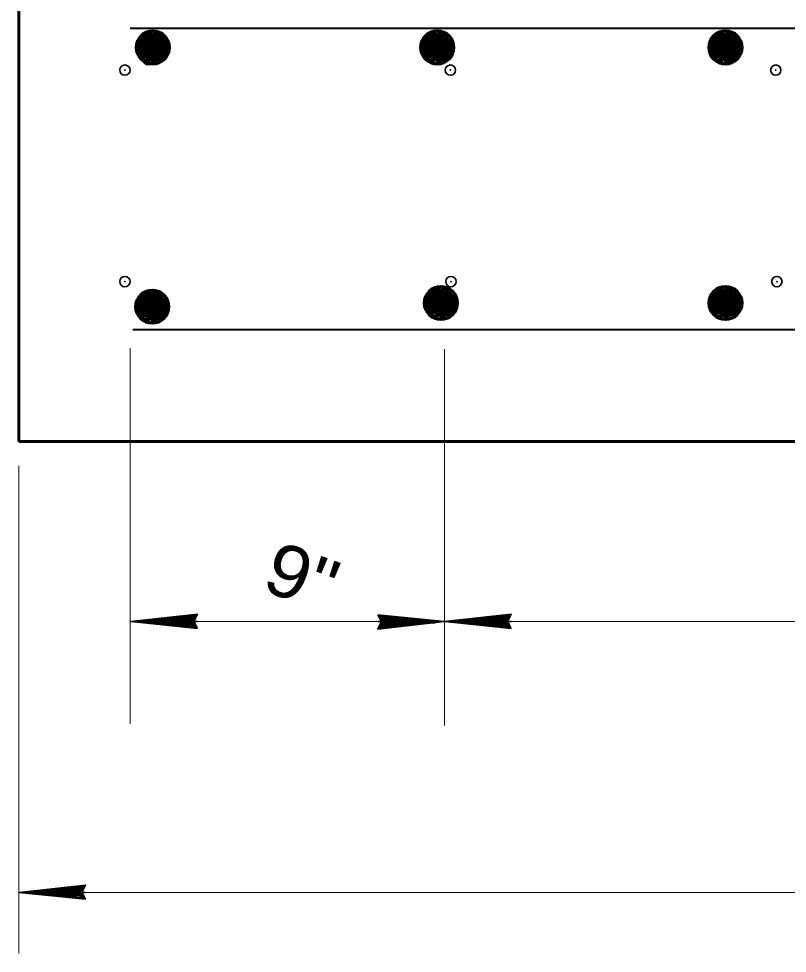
# Model space of a CAD drawing. Extents: x 4.49 to 7.69, y 0.28 to 2.27.
# Drawn here: x 6.3495 to 6.4715, y 1.791 to 1.9394 of the extents above; entities that cross this region are included whole.
import ezdxf
from ezdxf.enums import TextEntityAlignment as Align

# ---------------------------------------------------------------- set-up
doc = ezdxf.new("R2010")
doc.units = 0
doc.header["$LTSCALE"] = 0.0033
doc.header["$PDMODE"] = 32
doc.header["$PDSIZE"] = 0.00165
doc.layers.add('1', color=7, linetype='Continuous', lineweight=35)

msp = doc.modelspace()

# ---------------------------------------------------------------- linework, layer by layer
at = {"layer": '1', "lineweight": 60}
for p, q in [((6.3495, 1.87225), (6.3495, 1.955583)), ((6.368917, 1.936417), (6.36875, 1.9335)), ((6.369167, 1.936417), (6.368917, 1.9335)), ((6.369333, 1.936417), (6.369167, 1.933417)), ((6.3695, 1.936417), (6.36925, 1.933417)), ((6.369667, 1.936417), (6.3695, 1.933417)), ((6.369917, 1.936417), (6.36975, 1.933417)), ((6.370167, 1.936417), (6.369917, 1.933417)), ((6.37025, 1.936333), (6.370083, 1.933417)), ((6.370417, 1.936333), (6.37025, 1.933417)), ((6.370583, 1.936333), (6.370417, 1.933417)), ((6.370833, 1.936333), (6.370583, 1.933417)), ((6.371, 1.936333), (6.370833, 1.933417)), ((6.37125, 1.93625), (6.371, 1.933333)), ((6.3715, 1.93625), (6.37125, 1.933333)), ((6.371667, 1.93625), (6.3715, 1.933333)), ((6.37175, 1.93625), (6.371583, 1.933333)), ((6.371917, 1.93625), (6.37175, 1.933333)), ((6.372, 1.93625), (6.371833, 1.933333)), ((6.37225, 1.936167), (6.372, 1.93325)), ((6.372417, 1.936167), (6.37225, 1.93325)), ((6.372583, 1.936167), (6.372333, 1.93325)), ((6.37275, 1.936167), (6.372583, 1.93325)), ((6.373, 1.936167), (6.372833, 1.93325)), ((6.37325, 1.93425), (6.373083, 1.936083)), ((6.414083, 1.936417), (6.413917, 1.9335)), ((6.414333, 1.936417), (6.414083, 1.9335)), ((6.4145, 1.936417), (6.414333, 1.933417)), ((6.414667, 1.936417), (6.414417, 1.933417)), ((6.414833, 1.936417), (6.414667, 1.933417)), ((6.415083, 1.936417), (6.414917, 1.933417)), ((6.415333, 1.936417), (6.415083, 1.933417)), ((6.415417, 1.936333), (6.41525, 1.933417)), ((6.415583, 1.936333), (6.415417, 1.933417)), ((6.41575, 1.936333), (6.415583, 1.933417)), ((6.416, 1.936333), (6.41575, 1.933417)), ((6.416167, 1.936333), (6.416, 1.933417)), ((6.416417, 1.93625), (6.416167, 1.933333)), ((6.416667, 1.93625), (6.416417, 1.933333)), ((6.416833, 1.93625), (6.416667, 1.933333)), ((6.416917, 1.93625), (6.41675, 1.933333)), ((6.417083, 1.93625), (6.416917, 1.933333)), ((6.417167, 1.93625), (6.417, 1.933333)), ((6.417417, 1.936167), (6.417167, 1.93325)), ((6.417583, 1.936167), (6.417417, 1.93325)), ((6.41775, 1.936167), (6.4175, 1.93325)), ((6.417917, 1.936167), (6.41775, 1.93325)), ((6.418167, 1.936167), (6.418, 1.93325)), ((6.418417, 1.93425), (6.41825, 1.936083)), ((6.459833, 1.936417), (6.459667, 1.9335)), ((6.460083, 1.936417), (6.459833, 1.9335)), ((6.46025, 1.936417), (6.460083, 1.933417)), ((6.460417, 1.936417), (6.460167, 1.933417)), ((6.460583, 1.936417), (6.460417, 1.933417)), ((6.460833, 1.936417), (6.460667, 1.933417)), ((6.461083, 1.936417), (6.460833, 1.933417)), ((6.461167, 1.936333), (6.461, 1.933417)), ((6.461333, 1.936333), (6.461167, 1.933417)), ((6.4615, 1.936333), (6.461333, 1.933417)), ((6.46175, 1.936333), (6.4615, 1.933417)), ((6.461917, 1.936333), (6.46175, 1.933417)), ((6.462167, 1.93625), (6.461917, 1.933333)), ((6.462417, 1.93625), (6.462167, 1.933333)), ((6.462583, 1.93625), (6.462417, 1.933333)), ((6.462667, 1.93625), (6.4625, 1.933333)), ((6.462833, 1.93625), (6.462667, 1.933333)), ((6.462917, 1.93625), (6.46275, 1.933333)), ((6.463167, 1.936167), (6.462917, 1.93325)), ((6.463333, 1.936167), (6.463167, 1.93325)), ((6.4635, 1.936167), (6.46325, 1.93325)), ((6.463667, 1.936167), (6.4635, 1.93325)), ((6.463917, 1.936167), (6.46375, 1.93325)), ((6.464167, 1.93425), (6.464, 1.936083)), ((6.37325, 1.93425), (6.3685, 1.9335)), ((6.418417, 1.93425), (6.413667, 1.9335)), ((6.464167, 1.93425), (6.459417, 1.9335)), ((6.414667, 1.895833), (6.4145, 1.892917)), ((6.414917, 1.895833), (6.414667, 1.892917)), ((6.415083, 1.895833), (6.414917, 1.892833)), ((6.41525, 1.895833), (6.415, 1.892833)), ((6.415417, 1.895833), (6.41525, 1.892833)), ((6.415667, 1.895833), (6.4155, 1.892833)), ((6.415917, 1.895833), (6.415667, 1.892833)), ((6.416, 1.89575), (6.415833, 1.892833)), ((6.416167, 1.89575), (6.416, 1.892833)), ((6.416333, 1.89575), (6.416167, 1.892833)), ((6.416583, 1.89575), (6.416333, 1.892833)), ((6.41675, 1.89575), (6.416583, 1.892833)), ((6.417, 1.895667), (6.41675, 1.89275)), ((6.41725, 1.895667), (6.417, 1.89275)), ((6.417417, 1.895667), (6.41725, 1.89275)), ((6.4175, 1.895667), (6.417333, 1.89275)), ((6.417667, 1.895667), (6.4175, 1.89275)), ((6.41775, 1.895667), (6.417583, 1.89275)), ((6.418, 1.895583), (6.41775, 1.892667)), ((6.418167, 1.895583), (6.418, 1.892667)), ((6.418333, 1.895583), (6.418083, 1.892667)), ((6.4185, 1.895583), (6.418333, 1.892667)), ((6.41875, 1.895583), (6.418583, 1.892667)), ((6.419, 1.893667), (6.418833, 1.8955)), ((6.459833, 1.895833), (6.459667, 1.892917)), ((6.460083, 1.895833), (6.459833, 1.892917)), ((6.46025, 1.895833), (6.460083, 1.892833)), ((6.460417, 1.895833), (6.460167, 1.892833)), ((6.460583, 1.895833), (6.460417, 1.892833)), ((6.460833, 1.895833), (6.460667, 1.892833)), ((6.461083, 1.895833), (6.460833, 1.892833)), ((6.461167, 1.89575), (6.461, 1.892833)), ((6.461333, 1.89575), (6.461167, 1.892833)), ((6.4615, 1.89575), (6.461333, 1.892833)), ((6.46175, 1.89575), (6.4615, 1.892833)), ((6.461917, 1.89575), (6.46175, 1.892833)), ((6.462167, 1.895667), (6.461917, 1.89275)), ((6.462417, 1.895667), (6.462167, 1.89275)), ((6.462583, 1.895667), (6.462417, 1.89275)), ((6.462667, 1.895667), (6.4625, 1.89275)), ((6.462833, 1.895667), (6.462667, 1.89275)), ((6.462917, 1.895667), (6.46275, 1.89275)), ((6.463167, 1.895583), (6.462917, 1.892667)), ((6.463333, 1.895583), (6.463167, 1.892667)), ((6.4635, 1.895583), (6.46325, 1.892667)), ((6.463667, 1.895583), (6.4635, 1.892667)), ((6.463917, 1.895583), (6.46375, 1.892667)), ((6.464167, 1.893667), (6.464, 1.8955)), ((6.368833, 1.89525), (6.368667, 1.892333)), ((6.369083, 1.89525), (6.368833, 1.892333)), ((6.36925, 1.89525), (6.369083, 1.89225)), ((6.369417, 1.89525), (6.369167, 1.89225)), ((6.369583, 1.89525), (6.369417, 1.89225)), ((6.369833, 1.89525), (6.369667, 1.89225)), ((6.370083, 1.89525), (6.369833, 1.89225)), ((6.370167, 1.895167), (6.37, 1.89225)), ((6.370333, 1.895167), (6.370167, 1.89225)), ((6.3705, 1.895167), (6.370333, 1.89225)), ((6.37075, 1.895167), (6.3705, 1.89225)), ((6.370917, 1.895167), (6.37075, 1.89225)), ((6.371167, 1.895083), (6.370917, 1.892167)), ((6.371417, 1.895083), (6.371167, 1.892167)), ((6.371583, 1.895083), (6.371417, 1.892167)), ((6.371667, 1.895083), (6.3715, 1.892167)), ((6.371833, 1.895083), (6.371667, 1.892167)), ((6.371917, 1.895083), (6.37175, 1.892167)), ((6.372167, 1.895), (6.371917, 1.892083)), ((6.372333, 1.895), (6.372167, 1.892083)), ((6.3725, 1.895), (6.37225, 1.892083)), ((6.372667, 1.895), (6.3725, 1.892083)), ((6.372917, 1.895), (6.37275, 1.892083)), ((6.373167, 1.893083), (6.373, 1.894917)), ((6.373167, 1.893083), (6.368417, 1.892333)), ((6.419, 1.893667), (6.41425, 1.892917)), ((6.464167, 1.893667), (6.459417, 1.892917))]:
    msp.add_line(p, q, dxfattribs=at)
at = {"layer": '1', "lineweight": 40}
for p, q in [((6.367167, 1.937917), (6.831833, 1.937917)), ((6.371, 1.935917), (6.372333, 1.936917)), ((6.373083, 1.936083), (6.371833, 1.93725)), ((6.416167, 1.935917), (6.4175, 1.936917)), ((6.41825, 1.936083), (6.417, 1.93725)), ((6.461917, 1.935917), (6.46325, 1.936917)), ((6.464, 1.936083), (6.46275, 1.93725)), ((6.368667, 1.936417), (6.37325, 1.93425)), ((6.368833, 1.935417), (6.372667, 1.93475)), ((6.368917, 1.936), (6.372833, 1.93525)), ((6.368917, 1.935833), (6.372833, 1.935083)), ((6.368917, 1.935583), (6.37275, 1.934833)), ((6.369, 1.936417), (6.372917, 1.93575)), ((6.369, 1.93625), (6.372917, 1.9355)), ((6.369083, 1.93675), (6.372917, 1.936083)), ((6.413833, 1.936417), (6.418417, 1.93425)), ((6.414, 1.935417), (6.417833, 1.93475)), ((6.414083, 1.936), (6.418, 1.93525)), ((6.414083, 1.935833), (6.418, 1.935083)), ((6.414083, 1.935583), (6.417917, 1.934833)), ((6.414167, 1.936417), (6.418083, 1.93575)), ((6.414167, 1.93625), (6.418083, 1.9355)), ((6.41425, 1.93675), (6.418083, 1.936083)), ((6.459583, 1.936417), (6.464167, 1.93425)), ((6.45975, 1.935417), (6.463583, 1.93475)), ((6.459833, 1.936), (6.46375, 1.93525)), ((6.459833, 1.935833), (6.46375, 1.935083)), ((6.459833, 1.935583), (6.463667, 1.934833)), ((6.459917, 1.936417), (6.463833, 1.93575)), ((6.459917, 1.93625), (6.463833, 1.9355)), ((6.46, 1.93675), (6.463833, 1.936083)), ((6.368583, 1.934167), (6.3725, 1.933417)), ((6.368583, 1.934), (6.372417, 1.93325)), ((6.368667, 1.934583), (6.372583, 1.933833)), ((6.36875, 1.935), (6.372583, 1.93425)), ((6.36875, 1.934833), (6.372583, 1.934083)), ((6.368833, 1.93525), (6.372667, 1.9345)), ((6.41375, 1.934167), (6.417667, 1.933417)), ((6.41375, 1.934), (6.417583, 1.93325)), ((6.413833, 1.934583), (6.41775, 1.933833)), ((6.413917, 1.935), (6.41775, 1.93425)), ((6.413917, 1.934833), (6.41775, 1.934083)), ((6.414, 1.93525), (6.417833, 1.9345)), ((6.4595, 1.934167), (6.463417, 1.933417)), ((6.4595, 1.934), (6.463333, 1.93325)), ((6.459583, 1.934583), (6.4635, 1.933833)), ((6.459667, 1.935), (6.4635, 1.93425)), ((6.459667, 1.934833), (6.4635, 1.934083)), ((6.45975, 1.93525), (6.463583, 1.9345)), ((6.3685, 1.933667), (6.372333, 1.932917)), ((6.3685, 1.9335), (6.372333, 1.93275)), ((6.368583, 1.93375), (6.372417, 1.933083)), ((6.372833, 1.93325), (6.369083, 1.932833)), ((6.413667, 1.933667), (6.4175, 1.932917)), ((6.413667, 1.9335), (6.4175, 1.93275)), ((6.41375, 1.93375), (6.417583, 1.933083)), ((6.418, 1.93325), (6.41425, 1.932833)), ((6.459417, 1.933667), (6.46325, 1.932917)), ((6.459417, 1.9335), (6.46325, 1.93275)), ((6.4595, 1.93375), (6.463333, 1.933083)), ((6.46375, 1.93325), (6.46, 1.932833)), ((6.369, 1.895583), (6.372833, 1.894917)), ((6.370917, 1.89475), (6.37225, 1.89575)), ((6.373, 1.894917), (6.37175, 1.896083)), ((6.414417, 1.895833), (6.419, 1.893667)), ((6.414667, 1.895417), (6.418583, 1.894667)), ((6.41475, 1.895833), (6.418667, 1.895167)), ((6.41475, 1.895667), (6.418667, 1.894917)), ((6.414833, 1.896167), (6.418667, 1.8955)), ((6.41675, 1.895333), (6.418083, 1.896333)), ((6.418833, 1.8955), (6.417583, 1.896667)), ((6.459583, 1.895833), (6.464167, 1.893667)), ((6.459833, 1.895417), (6.46375, 1.894667)), ((6.459917, 1.895833), (6.463833, 1.895167)), ((6.459917, 1.895667), (6.463833, 1.894917)), ((6.46, 1.896167), (6.463833, 1.8955)), ((6.461917, 1.895333), (6.46325, 1.896333)), ((6.464, 1.8955), (6.46275, 1.896667)), ((6.368583, 1.89525), (6.373167, 1.893083)), ((6.368667, 1.893833), (6.3725, 1.893083)), ((6.36875, 1.89425), (6.372583, 1.893583)), ((6.36875, 1.894083), (6.372583, 1.893333)), ((6.368833, 1.894833), (6.37275, 1.894083)), ((6.368833, 1.894667), (6.37275, 1.893917)), ((6.368833, 1.894417), (6.372667, 1.893667)), ((6.368917, 1.89525), (6.372833, 1.894583)), ((6.368917, 1.895083), (6.372833, 1.894333)), ((6.414417, 1.894), (6.418333, 1.89325)), ((6.4145, 1.894417), (6.418333, 1.893667)), ((6.4145, 1.89425), (6.418333, 1.8935)), ((6.414583, 1.894833), (6.418417, 1.894167)), ((6.414583, 1.894667), (6.418417, 1.893917)), ((6.414667, 1.89525), (6.418583, 1.8945)), ((6.414667, 1.895), (6.4185, 1.89425)), ((6.459583, 1.894), (6.4635, 1.89325)), ((6.459667, 1.894417), (6.4635, 1.893667)), ((6.459667, 1.89425), (6.4635, 1.8935)), ((6.45975, 1.894833), (6.463583, 1.894167)), ((6.45975, 1.894667), (6.463583, 1.893917)), ((6.459833, 1.89525), (6.46375, 1.8945)), ((6.459833, 1.895), (6.463667, 1.89425)), ((6.368417, 1.8925), (6.37225, 1.89175)), ((6.368417, 1.892333), (6.37225, 1.891583)), ((6.3685, 1.893), (6.372417, 1.89225)), ((6.3685, 1.892833), (6.372333, 1.892083)), ((6.3685, 1.892583), (6.372333, 1.891917)), ((6.368583, 1.893417), (6.3725, 1.892667)), ((6.368667, 1.893667), (6.3725, 1.892917)), ((6.41425, 1.893083), (6.418083, 1.892333)), ((6.41425, 1.892917), (6.418083, 1.892167)), ((6.414333, 1.893583), (6.41825, 1.892833)), ((6.414333, 1.893417), (6.418167, 1.892667)), ((6.414333, 1.893167), (6.418167, 1.8925)), ((6.418583, 1.892667), (6.414833, 1.89225)), ((6.459417, 1.893083), (6.46325, 1.892333)), ((6.459417, 1.892917), (6.46325, 1.892167)), ((6.4595, 1.893583), (6.463417, 1.892833)), ((6.4595, 1.893417), (6.463333, 1.892667)), ((6.4595, 1.893167), (6.463333, 1.8925)), ((6.46375, 1.892667), (6.46, 1.89225)), ((6.37275, 1.892083), (6.369, 1.891667)), ((6.367583, 1.890083), (6.831667, 1.890083))]:
    msp.add_line(p, q, dxfattribs=at)
at = {"layer": '1', "lineweight": 13}
for p, q in [((6.367167, 1.887083), (6.367167, 1.827417)), ((6.417083, 1.886917), (6.417083, 1.827167)), ((6.3495, 1.868417), (6.3495, 1.791)), ((6.367583, 1.843667), (6.831667, 1.843667)), ((6.349417, 1.800667), (6.84875, 1.800667))]:
    msp.add_line(p, q, dxfattribs=at)
at = {"layer": '1'}
for p, q in [((6.377833, 1.843667), (6.36725, 1.843667)), ((6.377583, 1.842833), (6.36975, 1.843833)), ((6.377583, 1.842833), (6.36975, 1.843667)), ((6.377583, 1.842667), (6.36975, 1.843583)), ((6.377583, 1.842667), (6.36975, 1.843583)), ((6.377583, 1.84275), (6.36975, 1.843583)), ((6.377583, 1.84475), (6.37025, 1.843917)), ((6.377583, 1.844583), (6.37025, 1.843833)), ((6.377583, 1.8445), (6.37025, 1.843667)), ((6.377667, 1.844333), (6.370333, 1.843583)), ((6.4065, 1.843667), (6.417083, 1.843667)), ((6.406667, 1.843), (6.414, 1.84375)), ((6.40675, 1.844667), (6.414583, 1.84375)), ((6.40675, 1.844667), (6.414583, 1.84375)), ((6.40675, 1.844583), (6.414583, 1.84375)), ((6.40675, 1.8445), (6.414583, 1.843667)), ((6.40675, 1.8445), (6.414583, 1.8435)), ((6.40675, 1.842833), (6.414083, 1.843667)), ((6.40675, 1.84275), (6.414083, 1.8435)), ((6.40675, 1.842583), (6.414083, 1.843417)), ((6.427667, 1.843667), (6.417083, 1.843667)), ((6.427417, 1.842833), (6.419583, 1.843833)), ((6.427417, 1.842833), (6.419583, 1.843667)), ((6.427417, 1.842667), (6.419583, 1.843583)), ((6.427417, 1.842667), (6.419583, 1.843583)), ((6.427417, 1.84275), (6.419583, 1.843583)), ((6.427417, 1.84475), (6.420083, 1.843917)), ((6.427417, 1.844583), (6.420083, 1.843833)), ((6.427417, 1.8445), (6.420083, 1.843667)), ((6.4275, 1.844333), (6.420167, 1.843583)), ((6.360083, 1.800667), (6.3495, 1.800667)), ((6.359833, 1.799833), (6.352, 1.800833)), ((6.359833, 1.799833), (6.352, 1.800667)), ((6.359833, 1.799667), (6.352, 1.800583)), ((6.359833, 1.799667), (6.352, 1.800583)), ((6.359833, 1.79975), (6.352, 1.800583)), ((6.359833, 1.80175), (6.3525, 1.800917)), ((6.359833, 1.801583), (6.3525, 1.800833)), ((6.359833, 1.8015), (6.3525, 1.800667)), ((6.359917, 1.801333), (6.352583, 1.800583))]:
    msp.add_line(p, q, dxfattribs=at)
at = {"layer": '1', "lineweight": 60}
for points in [[(6.3495, 1.87225), (6.8495, 1.87225), (6.8495, 1.955583)], [(6.372333, 1.93275), (6.372333, 1.936917), (6.370667, 1.93225), (6.371167, 1.937417), (6.369083, 1.932833), (6.369833, 1.937333), (6.371417, 1.932333), (6.36825, 1.935667), (6.373083, 1.936083), (6.369833, 1.932417), (6.371833, 1.93725), (6.368667, 1.936417), (6.3685, 1.9335)], [(6.369083, 1.932833), (6.370583, 1.935083), (6.368417, 1.936), (6.370417, 1.937417), (6.370583, 1.935167), (6.37225, 1.932833), (6.36825, 1.935167), (6.371, 1.935917)], [(6.371833, 1.93725), (6.370583, 1.935083), (6.372833, 1.93325)], [(6.4175, 1.93275), (6.4175, 1.936917), (6.415833, 1.93225), (6.416333, 1.937417), (6.41425, 1.932833), (6.415, 1.937333), (6.416583, 1.932333), (6.413417, 1.935667), (6.41825, 1.936083), (6.415, 1.932417), (6.417, 1.93725), (6.413833, 1.936417), (6.413667, 1.9335)], [(6.41425, 1.932833), (6.41575, 1.935083), (6.413583, 1.936), (6.415583, 1.937417), (6.41575, 1.935167), (6.417417, 1.932833), (6.413417, 1.935167), (6.416167, 1.935917)], [(6.417, 1.93725), (6.41575, 1.935083), (6.418, 1.93325)], [(6.46325, 1.93275), (6.46325, 1.936917), (6.461583, 1.93225), (6.462083, 1.937417), (6.46, 1.932833), (6.46075, 1.937333), (6.462333, 1.932333), (6.459167, 1.935667), (6.464, 1.936083), (6.46075, 1.932417), (6.46275, 1.93725), (6.459583, 1.936417), (6.459417, 1.9335)], [(6.46, 1.932833), (6.4615, 1.935083), (6.459333, 1.936), (6.461333, 1.937417), (6.4615, 1.935167), (6.463167, 1.932833), (6.459167, 1.935167), (6.461917, 1.935917)], [(6.46275, 1.93725), (6.4615, 1.935083), (6.46375, 1.93325)], [(6.368083, 1.93475), (6.37325, 1.935417), (6.368667, 1.936417)], [(6.41325, 1.93475), (6.418417, 1.935417), (6.413833, 1.936417)], [(6.459, 1.93475), (6.464167, 1.935417), (6.459583, 1.936417)], [(6.418083, 1.892167), (6.418083, 1.896333), (6.416417, 1.891667), (6.416917, 1.896833), (6.414833, 1.89225), (6.415583, 1.89675), (6.417167, 1.89175), (6.414, 1.895083), (6.418833, 1.8955), (6.415583, 1.891833), (6.417583, 1.896667), (6.414417, 1.895833), (6.41425, 1.892917)], [(6.414833, 1.89225), (6.416333, 1.8945), (6.414167, 1.895417), (6.416167, 1.896833), (6.416333, 1.894583), (6.418, 1.89225), (6.414, 1.894583), (6.41675, 1.895333)], [(6.46325, 1.892167), (6.46325, 1.896333), (6.461583, 1.891667), (6.462083, 1.896833), (6.46, 1.89225), (6.46075, 1.89675), (6.462333, 1.89175), (6.459167, 1.895083), (6.464, 1.8955), (6.46075, 1.891833), (6.46275, 1.896667), (6.459583, 1.895833), (6.459417, 1.892917)], [(6.46, 1.89225), (6.4615, 1.8945), (6.459333, 1.895417), (6.461333, 1.896833), (6.4615, 1.894583), (6.463167, 1.89225), (6.459167, 1.894583), (6.461917, 1.895333)], [(6.37225, 1.891583), (6.37225, 1.89575), (6.370583, 1.891083), (6.371083, 1.89625), (6.369, 1.891667), (6.36975, 1.896167), (6.371333, 1.891167), (6.368167, 1.8945), (6.373, 1.894917), (6.36975, 1.89125), (6.37175, 1.896083), (6.368583, 1.89525), (6.368417, 1.892333)], [(6.369, 1.891667), (6.3705, 1.893917), (6.368333, 1.894833), (6.370333, 1.89625), (6.3705, 1.894), (6.372167, 1.891667), (6.368167, 1.894), (6.370917, 1.89475)], [(6.37175, 1.896083), (6.3705, 1.893917), (6.37275, 1.892083)], [(6.413833, 1.894167), (6.419, 1.894833), (6.414417, 1.895833)], [(6.417583, 1.896667), (6.416333, 1.8945), (6.418583, 1.892667)], [(6.459, 1.894167), (6.464167, 1.894833), (6.459583, 1.895833)], [(6.46275, 1.896667), (6.4615, 1.8945), (6.46375, 1.892667)], [(6.368, 1.893583), (6.373167, 1.89425), (6.368583, 1.89525)]]:
    msp.add_lwpolyline(points, dxfattribs=at)
at = {"layer": '1', "lineweight": 40}
for points in [[(6.3685, 1.9335), (6.370583, 1.93225), (6.372333, 1.93275), (6.37325, 1.93425)], [(6.413667, 1.9335), (6.41575, 1.93225), (6.4175, 1.93275), (6.418417, 1.93425)], [(6.459417, 1.9335), (6.4615, 1.93225), (6.46325, 1.93275), (6.464167, 1.93425)], [(6.368417, 1.892333), (6.3705, 1.891083), (6.37225, 1.891583), (6.373167, 1.893083)], [(6.41425, 1.892917), (6.416333, 1.891667), (6.418083, 1.892167), (6.419, 1.893667)], [(6.459417, 1.892917), (6.4615, 1.891667), (6.46325, 1.892167), (6.464167, 1.893667)]]:
    msp.add_lwpolyline(points, dxfattribs=at)
at = {"layer": '1'}
for points in [[(6.377833, 1.842583), (6.36725, 1.843667), (6.377833, 1.844833), (6.37725, 1.843667)], [(6.427667, 1.842583), (6.417083, 1.843667), (6.427667, 1.844833), (6.427083, 1.843667)], [(6.377083, 1.843583), (6.372417, 1.8435), (6.372417, 1.843583), (6.373333, 1.843583), (6.377083, 1.8435), (6.374083, 1.843417), (6.37725, 1.843333), (6.375, 1.84325), (6.37725, 1.843167), (6.37375, 1.843417), (6.369083, 1.843583), (6.37, 1.843833), (6.36875, 1.843833), (6.377083, 1.843833), (6.374667, 1.844), (6.37725, 1.844), (6.371917, 1.843583), (6.37725, 1.84425)], [(6.4065, 1.84475), (6.417083, 1.843667), (6.4065, 1.8425), (6.407083, 1.843667)], [(6.40725, 1.84375), (6.411917, 1.843833), (6.411917, 1.84375), (6.411, 1.84375), (6.40725, 1.843833), (6.41025, 1.843917), (6.407083, 1.844), (6.409333, 1.844083), (6.407083, 1.844167), (6.410583, 1.843917), (6.41525, 1.84375), (6.414333, 1.8435), (6.415583, 1.8435), (6.40725, 1.8435), (6.409667, 1.843333), (6.407083, 1.843333), (6.412417, 1.84375), (6.407083, 1.843083)], [(6.426917, 1.843583), (6.42225, 1.8435), (6.42225, 1.843583), (6.423167, 1.843583), (6.426917, 1.8435), (6.423917, 1.843417), (6.427083, 1.843333), (6.424833, 1.84325), (6.427083, 1.843167), (6.423583, 1.843417), (6.418917, 1.843583), (6.419833, 1.843833), (6.418583, 1.843833), (6.426917, 1.843833), (6.4245, 1.844), (6.427083, 1.844), (6.42175, 1.843583), (6.427083, 1.84425)], [(6.360083, 1.799583), (6.3495, 1.800667), (6.360083, 1.801833), (6.3595, 1.800667)], [(6.359333, 1.800583), (6.354667, 1.8005), (6.354667, 1.800583), (6.355583, 1.800583), (6.359333, 1.8005), (6.356333, 1.800417), (6.3595, 1.800333), (6.35725, 1.80025), (6.3595, 1.800167), (6.356, 1.800417), (6.351333, 1.800583), (6.35225, 1.800833), (6.351, 1.800833), (6.359333, 1.800833), (6.356917, 1.801), (6.3595, 1.801), (6.354167, 1.800583), (6.3595, 1.80125)]]:
    msp.add_lwpolyline(points, close=True, dxfattribs=at)
for points in [[(6.377083, 1.843583), (6.3775, 1.842833), (6.37725, 1.843083), (6.377083, 1.843417), (6.376833, 1.843333), (6.377, 1.843), (6.377167, 1.84375), (6.377333, 1.84425), (6.377583, 1.844667)], [(6.40725, 1.84375), (6.406833, 1.8445), (6.407083, 1.84425), (6.40725, 1.843917), (6.4075, 1.844), (6.407333, 1.844333), (6.407167, 1.843583), (6.407, 1.843083), (6.40675, 1.842667)], [(6.426917, 1.843583), (6.427333, 1.842833), (6.427083, 1.843083), (6.426917, 1.843417), (6.426667, 1.843333), (6.426833, 1.843), (6.427, 1.84375), (6.427167, 1.84425), (6.427417, 1.844667)], [(6.359333, 1.800583), (6.35975, 1.799833), (6.3595, 1.800083), (6.359333, 1.800417), (6.359083, 1.800333), (6.35925, 1.8), (6.359417, 1.80075), (6.359583, 1.80125), (6.359833, 1.801667)]]:
    msp.add_lwpolyline(points, dxfattribs=at)
at = {"layer": '1', "lineweight": 60}
for centre in [(6.37075, 1.93485), (6.415917, 1.93485), (6.461667, 1.93485), (6.4165, 1.894267), (6.461667, 1.894267), (6.370667, 1.893683)]:
    msp.add_circle(centre, 0.00264, dxfattribs=at)
at = {"layer": '1'}
for p in [(6.37, 1.932917), (6.415833, 1.932917), (6.46175, 1.932917), (6.366333, 1.93125), (6.418, 1.93125), (6.469667, 1.93125), (6.366333, 1.897667), (6.418083, 1.897667), (6.469833, 1.897667), (6.37, 1.892917), (6.41575, 1.892917), (6.461583, 1.892917)]:
    msp.add_point(p, dxfattribs=at)

# ---------------------------------------------------------------- texts
at = {"layer": '1', "width": 1.1}
msp.add_text('9"', height=0.008333, rotation=340, dxfattribs=at).set_placement((6.392992, 1.84688), align=Align.CENTER)

doc.saveas('drawing.dxf')
